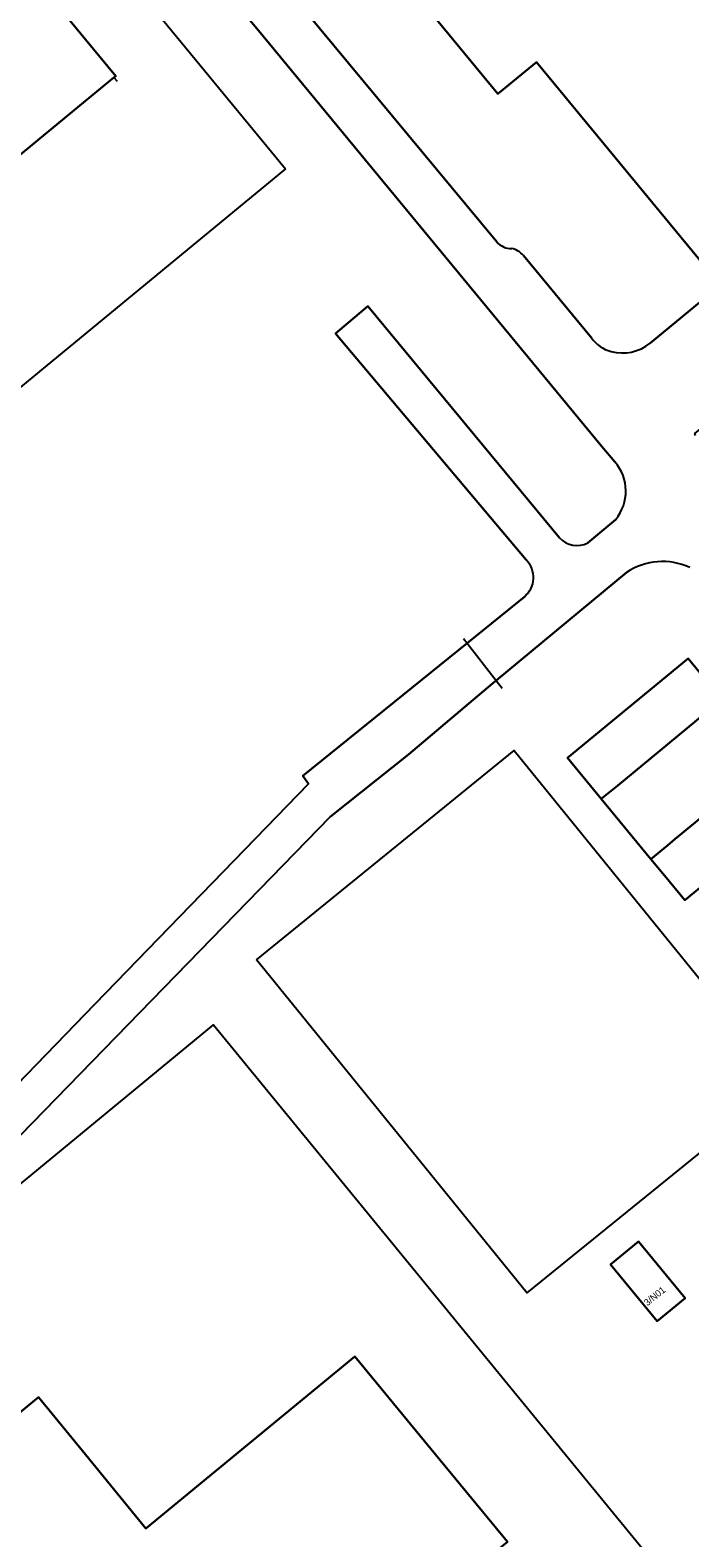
# Model space of a CAD drawing. Extents: x 156141 to 158132, y 385651 to 388333.
# Drawn here: x 156991.8 to 157089.1, y 386652.3 to 386874.6 of the extents above; entities that cross this region are included whole.
import ezdxf

# ---------------------------------------------------------------- set-up
doc = ezdxf.new("R2010")
doc.units = 0
for name, color, linetype in [('IMGEO_Erf', 7, 'Continuous'), ('IMGEO_Hek', 7, 'Continuous'), ('IMGEO_Pand', 7, 'Continuous'), ('IMGEO_Pand_nummerreeks', 7, 'Continuous'), ('IMGEO_Pand_vergunning_verleend', 7, 'Continuous'), ('IMGEO_Rijbaan_lokaal_open', 7, 'Continuous')]:
    doc.layers.add(name, color=color, linetype=linetype)

msp = doc.modelspace()

# ---------------------------------------------------------------- linework, layer by layer
at = {"layer": 'IMGEO_Erf'}
for points in [[(157066.45, 386869.91), (157060.78, 386865.23), (157041.56, 386888.57), (157047.21, 386893.24), (157016.15, 386930.98), (157014.26, 386929.42), (157008.33, 386929.92), (157002.98, 386925.56)], [(157001.44, 386914.91), (157021.68, 386890.42), (157025.76, 386885.45), (157058.21, 386846.34), (157060.62, 386843.41)], [(157078.01, 386810.98), (157076.11, 386813.25), (157042.17, 386854.32), (157026.17, 386873.74), (156992.74, 386913.98)], [(156975.66, 386902.77), (157000, 386873.24), (157004.43, 386867.87), (157004.18, 386867.66), (157000, 386864.22), (156951.3, 386824.08)], [(157083.22, 386828.47), (157093.59, 386837.01), (157066.45, 386869.91)], [(157064.52, 386841.41), (157074.56, 386829.29)], [(157064.93, 386796.51), (157036.83, 386829.91), (157041.62, 386833.93), (157069.86, 386799.79)], [(157074.03, 386799.05), (157078.13, 386802.48)], [(157079.74, 386794.67), (157060.52, 386778.76), (157059.95, 386778.28), (157047.58, 386767.81), (157036.03, 386758.64), (157025.63, 386747.93), (156986.8, 386708.06), (156987.93, 386706.73), (156922.25, 386652.43), (156921.77, 386652.52)], [(156981.68, 386711.24), (156988.46, 386717.66), (157001.36, 386731.03), (157013.9, 386743.93), (157023.49, 386753.81), (157032.83, 386763.49), (157032.01, 386764.67), (157056.24, 386784.27), (157064.67, 386791.09)], [(157104.22, 386770.79), (157102.56, 386769.59), (157103.24, 386768.71), (157101.09, 386767.08), (157105.93, 386761.24), (157106.09, 386761.05), (157092.73, 386750), (157088.32, 386746.36), (157085.32, 386750), (157083.32, 386752.42), (157076.01, 386761.28), (157071.02, 386767.34), (157088.79, 386782), (157093.79, 386775.93), (157098.13, 386779.5)]]:
    msp.add_lwpolyline(points, dxfattribs=at)
for points in [[(157077.38, 386692.61), (157081.51, 386696.02), (157088.38, 386687.69), (157084.25, 386684.29)], [(157015.84, 386613.64), (157025.46, 386601.92), (157002.08, 386582.67), (157000, 386580.95), (156998.22, 386579.49), (156988.5, 386591.31), (157000, 386600.76), (157004.2, 386604.21), (157002.5, 386606.28), (157006.07, 386609.22), (157000, 386616.6), (156979.09, 386642.04), (156969.51, 386653.7), (156993.07, 386673.07), (157000, 386664.6), (157008.89, 386653.73), (157039.69, 386679.09), (157049.27, 386667.44), (157062.16, 386651.76)]]:
    msp.add_lwpolyline(points, close=True, dxfattribs=at)
for centre, radius, start, end in [((157062.73, 386845.21), 2.78, 220.3423, 271.7037), ((157062.14, 386839.38), 3.13, 40.3504, 77.505), ((157078.83, 386832.28), 5.22, 214.9869, 254.7007), ((157079.1, 386833.65), 6.62, 255.5709, 308.4707), ((157073.06, 386806.66), 6.57, 320.5156, 41.0767), ((157072.41, 386802.02), 3.39, 221.2465, 298.6639), ((157062.38, 386793.92), 3.64, 309.0219, 45.3957), ((157085.06, 386786.67), 9.61, 65.4413, 123.6381)]:
    msp.add_arc(centre, radius, start, end, dxfattribs=at)
at = {"layer": 'IMGEO_Hek'}
for points in [[(156981.2, 386912.78), (157029.48, 386854.2)], [(157004.69, 386867.04), (157004.18, 386867.66)], [(157029.48, 386854.2), (156858.45, 386713.3)], [(157055.72, 386784.94), (157056.24, 386784.27), (157060.52, 386778.76), (157061.4, 386777.63)], [(156915.96, 386643.49), (156962.48, 386681.55), (156964.52, 386683.22), (157018.84, 386727.99), (157084.51, 386647.83)]]:
    msp.add_lwpolyline(points, dxfattribs=at)
at = {"layer": 'IMGEO_Pand'}
for points in [[(156951.3, 386824.08), (157000, 386864.22), (157004.18, 386867.66), (157004.43, 386867.87), (157000, 386873.24), (156975.66, 386902.77)], [(157041.56, 386888.57), (157060.78, 386865.23), (157066.45, 386869.91), (157093.59, 386837.01), (157100.14, 386829.08), (157183.76, 386898.02)]]:
    msp.add_lwpolyline(points, dxfattribs=at)
for points in [[(157093.79, 386775.93), (157088.79, 386782), (157071.02, 386767.34), (157076.01, 386761.28), (157078.44, 386763.28), (157079.56, 386764.21)], [(157085.32, 386750), (157088.32, 386746.36), (157092.73, 386750), (157106.09, 386761.05), (157105.93, 386761.24), (157101.09, 386767.08), (157095.58, 386762.53), (157086.87, 386755.35), (157085.75, 386754.42), (157083.32, 386752.42)], [(157088.38, 386687.69), (157081.51, 386696.02), (157077.38, 386692.61), (157084.25, 386684.29)], [(157002.08, 386582.67), (157025.46, 386601.92), (157015.84, 386613.64), (157062.16, 386651.76), (157049.27, 386667.44), (157039.69, 386679.09), (157008.89, 386653.73), (157000, 386664.6), (156993.07, 386673.07), (156969.51, 386653.7), (156979.09, 386642.04), (157000, 386616.6), (157006.07, 386609.22), (157002.5, 386606.28), (157004.2, 386604.21), (157000, 386600.76), (156988.5, 386591.31), (156998.22, 386579.49), (157000, 386580.95)]]:
    msp.add_lwpolyline(points, close=True, dxfattribs=at)
at = {"layer": 'IMGEO_Pand_vergunning_verleend'}
msp.add_lwpolyline([(157025.19, 386737.57), (157063.17, 386768.4), (157103.04, 386719.28), (157065.05, 386688.45)], close=True, dxfattribs=at)
at = {"layer": 'IMGEO_Rijbaan_lokaal_open'}
for points in [[(157060.62, 386843.41), (157058.21, 386846.34), (157025.76, 386885.45), (157021.68, 386890.42), (157001.44, 386914.91)], [(156992.74, 386913.98), (157026.17, 386873.74), (157042.17, 386854.32), (157076.11, 386813.25), (157078.01, 386810.98)], [(157074.56, 386829.29), (157064.52, 386841.41)], [(157089.9, 386814.87), (157089.78, 386815.17), (157102.7, 386825.8), (157100.14, 386829.08), (157093.59, 386837.01), (157083.22, 386828.47)], [(157041.62, 386833.93), (157036.83, 386829.91), (157064.93, 386796.51)], [(157069.86, 386799.79), (157041.62, 386833.93)], [(157078.13, 386802.48), (157074.03, 386799.05)], [(156921.77, 386652.52), (156922.25, 386652.43), (156987.93, 386706.73), (156986.8, 386708.06), (157025.63, 386747.93), (157036.03, 386758.64), (157047.58, 386767.81), (157059.95, 386778.28), (157060.52, 386778.76), (157079.74, 386794.67)], [(157064.67, 386791.09), (157056.24, 386784.27), (157032.01, 386764.67), (157032.83, 386763.49), (157023.49, 386753.81), (157013.9, 386743.93), (157001.36, 386731.03), (156988.46, 386717.66), (156981.68, 386711.24)], [(157098.13, 386779.5), (157093.79, 386775.93), (157079.56, 386764.21), (157078.44, 386763.28), (157076.01, 386761.28), (157083.32, 386752.42), (157085.75, 386754.42), (157086.87, 386755.35), (157095.58, 386762.53), (157101.09, 386767.08), (157103.24, 386768.71), (157102.56, 386769.59), (157104.22, 386770.79)]]:
    msp.add_lwpolyline(points, dxfattribs=at)
for centre, radius, start, end in [((157062.73, 386845.21), 2.78, 220.3423, 271.7037), ((157062.14, 386839.38), 3.13, 40.3504, 77.505), ((157078.83, 386832.28), 5.22, 214.9869, 254.7007), ((157079.1, 386833.65), 6.62, 255.5709, 308.4707), ((157073.06, 386806.66), 6.57, 320.5156, 41.0767), ((157072.41, 386802.02), 3.39, 221.2465, 298.6639), ((157062.38, 386793.92), 3.64, 309.0219, 45.3957), ((157085.06, 386786.67), 9.61, 65.4413, 123.6381)]:
    msp.add_arc(centre, radius, start, end, dxfattribs=at)

# ---------------------------------------------------------------- texts
at = {"layer": 'IMGEO_Pand_nummerreeks'}
msp.add_text('3/N01', height=1, rotation=39.0544, dxfattribs=at).set_placement((157082.81, 386686.45))

doc.saveas('drawing.dxf')
